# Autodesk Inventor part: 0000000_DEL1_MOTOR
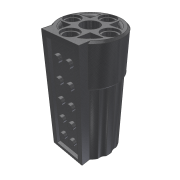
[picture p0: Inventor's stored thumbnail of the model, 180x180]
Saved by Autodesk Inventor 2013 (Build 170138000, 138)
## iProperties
Created: 2013-03
Part Number: 0000000_DEL1_MOTOR
Material: Generic
Document SubType Name: Modeling
Designer: perblt
Density: 1 g/cm^3
Translation Standard: STEP AP203
FileName: 0000000_DEL1_MOTOR
PreProcessor: PRO/ENGINEER BY PARAMETRIC TECHNOLOGY CORPORATION, 2010370
PostProcessor: Build: 138, Release: 2013 RTM - Date: Thu 03/01/2012
Sent Units: millimeter
Uncertainty: 0.005989625923235
Author: perblt
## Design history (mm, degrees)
node "0000000_DEL1_MOTOR1"
node "0000000_DEL1_MOTOR"
node "Base1"
